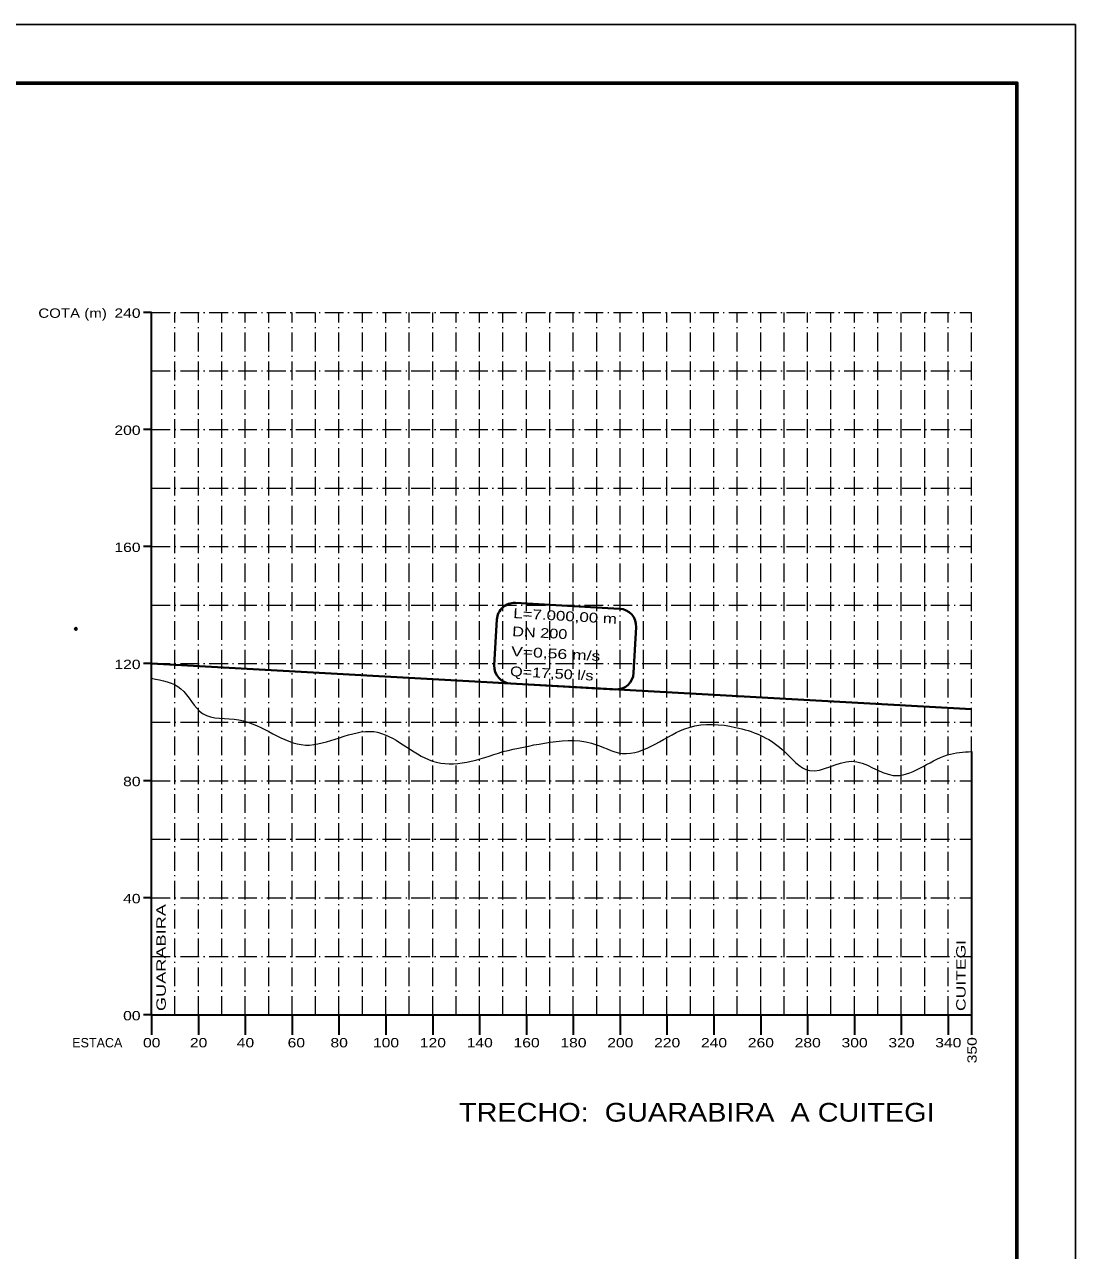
# Model space of a CAD drawing. Extents: x -4 to 42046, y -3 to 29697.
# Drawn here: x 33074 to 42046, y 19227 to 29697 of the extents above; entities that cross this region are included whole.
import ezdxf
from ezdxf.enums import TextEntityAlignment as Align

# ---------------------------------------------------------------- set-up
doc = ezdxf.new("R2010")
doc.units = 0
doc.header["$LTSCALE"] = 32
doc.header["$PDMODE"] = 32
doc.header["$PDSIZE"] = 16
doc.linetypes.add('DOT_DASHED', pattern=[7.7, 5, -1.2, 0.3, -1.2])
for name, color, linetype, lineweight in [('1', 7, 'DOT_DASHED', 13), ('24', 7, 'Continuous', 35), ('55', 7, 'Continuous', 13), ('62', 7, 'Continuous', 13), ('63', 7, 'Continuous', 25), ('9', 7, 'Continuous', 40)]:
    doc.layers.add(name, color=color, linetype=linetype, lineweight=lineweight)

msp = doc.modelspace()

# ---------------------------------------------------------------- linework, layer by layer
at = {"layer": '1'}
for p, q in [((34158.63, 27238.44), (41158.63, 27238.44)), ((34358.63, 21238.44), (34358.63, 27238.44)), ((34558.63, 21238.44), (34558.63, 27238.44)), ((34758.63, 21238.44), (34758.63, 27238.44)), ((34958.63, 21238.44), (34958.63, 27238.44)), ((35158.63, 21238.44), (35158.63, 27238.44)), ((35358.63, 21238.44), (35358.63, 27238.44)), ((35558.63, 21238.44), (35558.63, 27238.44)), ((35758.63, 21238.44), (35758.63, 27238.44)), ((35958.63, 21238.44), (35958.63, 27238.44)), ((36158.63, 21238.44), (36158.63, 27238.44)), ((36358.63, 21238.44), (36358.63, 27238.44)), ((36558.63, 21238.44), (36558.63, 27238.44)), ((36758.63, 21238.44), (36758.63, 27238.44)), ((36958.63, 21238.44), (36958.63, 27238.44)), ((37158.63, 21238.44), (37158.63, 27238.44)), ((37358.63, 21238.44), (37358.63, 27238.44)), ((37558.63, 21238.44), (37558.63, 27238.44)), ((37758.63, 21238.44), (37758.63, 27238.44)), ((37958.63, 21238.44), (37958.63, 27238.44)), ((38158.63, 21238.44), (38158.63, 27238.44)), ((38358.63, 21238.44), (38358.63, 27238.44)), ((38558.63, 21238.44), (38558.63, 27238.44)), ((38758.63, 21238.44), (38758.63, 27238.44)), ((38958.63, 21238.44), (38958.63, 27238.44)), ((39158.63, 21238.44), (39158.63, 27238.44)), ((39358.63, 21238.44), (39358.63, 27238.44)), ((39558.63, 21238.44), (39558.63, 27238.44)), ((39758.63, 21238.44), (39758.63, 27238.44)), ((39958.63, 21238.44), (39958.63, 27238.44)), ((40158.63, 21238.44), (40158.63, 27238.44)), ((40358.63, 21238.44), (40358.63, 27238.44)), ((40558.63, 21238.44), (40558.63, 27238.44)), ((40758.63, 21238.44), (40758.63, 27238.44)), ((40958.63, 21238.44), (40958.63, 27238.44)), ((41158.63, 21238.44), (41158.63, 27238.44)), ((34158.63, 26738.44), (41158.63, 26738.44)), ((34158.63, 26238.44), (41158.63, 26238.44)), ((34158.63, 25738.44), (41158.63, 25738.44)), ((34158.63, 25238.44), (41158.63, 25238.44)), ((34158.63, 24738.44), (41158.63, 24738.44)), ((34158.63, 24238.44), (41158.63, 24238.44)), ((34158.63, 23738.44), (41158.63, 23738.44)), ((34158.63, 23238.44), (41158.63, 23238.44)), ((34158.63, 22738.44), (41158.63, 22738.44)), ((34158.63, 22238.44), (41158.63, 22238.44)), ((34158.63, 21738.44), (41158.63, 21738.44))]:
    msp.add_line(p, q, dxfattribs=at)
at = {"layer": '55', "lineweight": 35}
msp.add_line((41158.63, 23488.44), (41158.63, 21238.44), dxfattribs=at)
at = {"layer": '55'}
for points in [[(34158.63, 24113.44), (34409.28, 24023.94), (34594.33, 23813.21), (34905.23, 23757.75), (35471.5, 23543.33), (36056.28, 23657.93), (36555.93, 23406.54), (37158.63, 23488.44)], [(37158.63, 23488.44), (37512.36, 23559.82), (37915.48, 23559.82), (38177.52, 23472.43), (38748.62, 23694.26), (39145.03, 23694.26), (39541.44, 23506.04), (39776.59, 23324.54), (40132.69, 23405.21), (40488.79, 23284.21), (40952.38, 23458.99), (41158.63, 23488.44)]]:
    msp.add_spline(points, degree=3, dxfattribs=at)
at = {"layer": '62', "lineweight": 35}
for p, q in [((34158.63, 27238.44), (34090.36, 27238.44)), ((34154.43, 27238.44), (34158.63, 27238.44)), ((34158.63, 21238.44), (34158.63, 27238.44)), ((34154.43, 26988.44), (34158.63, 26988.44)), ((34154.43, 26738.44), (34158.63, 26738.44)), ((34154.43, 26488.44), (34158.63, 26488.44)), ((34158.63, 26238.44), (34090.36, 26238.44)), ((34154.43, 26238.44), (34158.63, 26238.44)), ((34154.43, 25988.44), (34158.63, 25988.44)), ((34154.43, 25738.44), (34158.63, 25738.44)), ((34154.43, 25488.44), (34158.63, 25488.44)), ((34158.63, 25238.44), (34090.36, 25238.44)), ((34154.43, 25238.44), (34158.63, 25238.44)), ((34154.43, 24988.44), (34158.63, 24988.44)), ((34154.43, 24738.44), (34158.63, 24738.44)), ((34154.43, 24488.44), (34158.63, 24488.44)), ((34158.63, 24238.44), (34090.36, 24238.44)), ((34154.43, 24238.44), (34158.63, 24238.44)), ((34154.43, 23988.44), (34158.63, 23988.44)), ((34154.43, 23738.44), (34158.63, 23738.44)), ((34154.43, 23488.44), (34158.63, 23488.44)), ((34158.63, 23238.44), (34090.36, 23238.44)), ((34154.43, 23238.44), (34158.63, 23238.44)), ((34154.43, 22988.44), (34158.63, 22988.44)), ((34154.43, 22738.44), (34158.63, 22738.44)), ((34154.43, 22488.44), (34158.63, 22488.44)), ((34158.63, 22238.44), (34090.36, 22238.44)), ((34154.43, 22238.44), (34158.63, 22238.44)), ((34154.43, 21988.44), (34158.63, 21988.44)), ((34154.43, 21738.44), (34158.63, 21738.44)), ((34154.43, 21488.44), (34158.63, 21488.44)), ((34158.63, 21238.44), (34090.36, 21238.44)), ((34158.63, 21238.44), (34158.63, 21067.76)), ((34158.63, 21238.44), (41158.63, 21238.44)), ((34558.63, 21238.44), (34558.63, 21067.76)), ((34958.63, 21238.44), (34958.63, 21067.76)), ((35358.63, 21238.44), (35358.63, 21067.76)), ((35758.63, 21238.44), (35758.63, 21067.76)), ((36158.63, 21238.44), (36158.63, 21067.76)), ((36558.63, 21238.44), (36558.63, 21067.76)), ((36958.63, 21238.44), (36958.63, 21067.76)), ((37358.63, 21238.44), (37358.63, 21067.76)), ((37758.63, 21238.44), (37758.63, 21067.76)), ((38158.63, 21238.44), (38158.63, 21067.76)), ((38558.63, 21238.44), (38558.63, 21067.76)), ((38958.63, 21238.44), (38958.63, 21067.76)), ((39358.63, 21238.44), (39358.63, 21067.76)), ((39758.63, 21238.44), (39758.63, 21067.76)), ((40158.63, 21238.44), (40158.63, 21067.76)), ((40558.63, 21238.44), (40558.63, 21067.76)), ((40958.63, 21238.44), (40958.63, 21067.76)), ((41158.63, 21238.44), (41158.63, 21067.76))]:
    msp.add_line(p, q, dxfattribs=at)
at = {"layer": '62'}
for p, q in [((34154.43, 27188.44), (34158.63, 27188.44)), ((34154.43, 27138.44), (34158.63, 27138.44)), ((34154.43, 27088.44), (34158.63, 27088.44)), ((34154.43, 27038.44), (34158.63, 27038.44)), ((34154.43, 26938.44), (34158.63, 26938.44)), ((34154.43, 26888.44), (34158.63, 26888.44)), ((34154.43, 26838.44), (34158.63, 26838.44)), ((34154.43, 26788.44), (34158.63, 26788.44)), ((34154.43, 26688.44), (34158.63, 26688.44)), ((34154.43, 26638.44), (34158.63, 26638.44)), ((34154.43, 26588.44), (34158.63, 26588.44)), ((34154.43, 26538.44), (34158.63, 26538.44)), ((34154.43, 26438.44), (34158.63, 26438.44)), ((34154.43, 26388.44), (34158.63, 26388.44)), ((34154.43, 26338.44), (34158.63, 26338.44)), ((34154.43, 26288.44), (34158.63, 26288.44)), ((34154.43, 26188.44), (34158.63, 26188.44)), ((34154.43, 26138.44), (34158.63, 26138.44)), ((34154.43, 26088.44), (34158.63, 26088.44)), ((34154.43, 26038.44), (34158.63, 26038.44)), ((34154.43, 25938.44), (34158.63, 25938.44)), ((34154.43, 25888.44), (34158.63, 25888.44)), ((34154.43, 25838.44), (34158.63, 25838.44)), ((34154.43, 25788.44), (34158.63, 25788.44)), ((34154.43, 25688.44), (34158.63, 25688.44)), ((34154.43, 25638.44), (34158.63, 25638.44)), ((34154.43, 25588.44), (34158.63, 25588.44)), ((34154.43, 25538.44), (34158.63, 25538.44)), ((34154.43, 25438.44), (34158.63, 25438.44)), ((34154.43, 25388.44), (34158.63, 25388.44)), ((34154.43, 25338.44), (34158.63, 25338.44)), ((34154.43, 25288.44), (34158.63, 25288.44)), ((34154.43, 25188.44), (34158.63, 25188.44)), ((34154.43, 25138.44), (34158.63, 25138.44)), ((34154.43, 25088.44), (34158.63, 25088.44)), ((34154.43, 25038.44), (34158.63, 25038.44)), ((34154.43, 24938.44), (34158.63, 24938.44)), ((34154.43, 24888.44), (34158.63, 24888.44)), ((34154.43, 24838.44), (34158.63, 24838.44)), ((34154.43, 24788.44), (34158.63, 24788.44)), ((34154.43, 24688.44), (34158.63, 24688.44)), ((34154.43, 24638.44), (34158.63, 24638.44)), ((34154.43, 24588.44), (34158.63, 24588.44)), ((34154.43, 24538.44), (34158.63, 24538.44)), ((34154.43, 24438.44), (34158.63, 24438.44)), ((34154.43, 24388.44), (34158.63, 24388.44)), ((34154.43, 24338.44), (34158.63, 24338.44)), ((34154.43, 24288.44), (34158.63, 24288.44)), ((34154.43, 24188.44), (34158.63, 24188.44)), ((34154.43, 24138.44), (34158.63, 24138.44)), ((34154.43, 24088.44), (34158.63, 24088.44)), ((34154.43, 24038.44), (34158.63, 24038.44)), ((34154.43, 23938.44), (34158.63, 23938.44)), ((34154.43, 23888.44), (34158.63, 23888.44)), ((34154.43, 23838.44), (34158.63, 23838.44)), ((34154.43, 23788.44), (34158.63, 23788.44)), ((34154.43, 23688.44), (34158.63, 23688.44)), ((34154.43, 23638.44), (34158.63, 23638.44)), ((34154.43, 23588.44), (34158.63, 23588.44)), ((34154.43, 23538.44), (34158.63, 23538.44)), ((34154.43, 23438.44), (34158.63, 23438.44)), ((34154.43, 23388.44), (34158.63, 23388.44)), ((34154.43, 23338.44), (34158.63, 23338.44)), ((34154.43, 23288.44), (34158.63, 23288.44)), ((34154.43, 23188.44), (34158.63, 23188.44)), ((34154.43, 23138.44), (34158.63, 23138.44)), ((34154.43, 23088.44), (34158.63, 23088.44)), ((34154.43, 23038.44), (34158.63, 23038.44)), ((34154.43, 22938.44), (34158.63, 22938.44)), ((34154.43, 22888.44), (34158.63, 22888.44)), ((34154.43, 22838.44), (34158.63, 22838.44)), ((34154.43, 22788.44), (34158.63, 22788.44)), ((34154.43, 22688.44), (34158.63, 22688.44)), ((34154.43, 22638.44), (34158.63, 22638.44)), ((34154.43, 22588.44), (34158.63, 22588.44)), ((34154.43, 22538.44), (34158.63, 22538.44)), ((34154.43, 22438.44), (34158.63, 22438.44)), ((34154.43, 22388.44), (34158.63, 22388.44)), ((34154.43, 22338.44), (34158.63, 22338.44)), ((34154.43, 22288.44), (34158.63, 22288.44)), ((34154.43, 22188.44), (34158.63, 22188.44)), ((34154.43, 22138.44), (34158.63, 22138.44)), ((34154.43, 22088.44), (34158.63, 22088.44)), ((34154.43, 22038.44), (34158.63, 22038.44)), ((34154.43, 21938.44), (34158.63, 21938.44)), ((34154.43, 21888.44), (34158.63, 21888.44)), ((34154.43, 21838.44), (34158.63, 21838.44)), ((34154.43, 21788.44), (34158.63, 21788.44)), ((34154.43, 21688.44), (34158.63, 21688.44)), ((34154.43, 21638.44), (34158.63, 21638.44)), ((34154.43, 21588.44), (34158.63, 21588.44)), ((34154.43, 21538.44), (34158.63, 21538.44)), ((34154.43, 21438.44), (34158.63, 21438.44)), ((34154.43, 21388.44), (34158.63, 21388.44)), ((34154.43, 21338.44), (34158.63, 21338.44)), ((34154.43, 21288.44), (34158.63, 21288.44))]:
    msp.add_line(p, q, dxfattribs=at)
at = {"layer": '63'}
for p in [(-4.21, 29697.03), (42045.8, -2.97), (42045.8, -2.97)]:
    msp.add_line(p, (42045.8, 29697.03), dxfattribs=at)
msp.add_lwpolyline([(-4.21, -2.97), (42045.8, -2.97), (42045.8, 29697.03)], dxfattribs=at)
at = {"layer": '63', "lineweight": 60}
msp.add_lwpolyline([(1245.8, 29197.03), (41545.8, 29197.03), (41545.8, 497.03), (32795.79, 497.03)], dxfattribs=at)
at = {"layer": '63'}
msp.add_point((41545.8, 29197.03), dxfattribs=at)
at = {"layer": '9'}
for p, q in [((37264.6, 24756.83), (38154.08, 24707.3)), ((37106.49, 24615.4), (37084.8, 24225.74)), ((38295.5, 24549.19), (38273.81, 24159.53)), ((34158.63, 24238.44), (41158.63, 23848.67)), ((37226.23, 24067.63), (38115.7, 24018.1))]:
    msp.add_line(p, q, dxfattribs=at)
for centre, start, end in [((37256.26, 24607.06), 86.81296, 176.81296), ((38145.74, 24557.53), 356.81296, 86.81296), ((37234.57, 24217.4), 176.81296, 266.81296), ((38124.04, 24167.87), 266.81296, 356.81296)]:
    msp.add_arc(centre, 150, start, end, dxfattribs=at)
msp.add_point((33513.06, 24535.3), dxfattribs=at)

# ---------------------------------------------------------------- texts
at = {"layer": '24'}
for s, width, p in [('COTA (m)', 1.2, (33776.77, 27192.04)), ('240', 1.25, (34064.79, 27192.04)), ('200', 1.25, (34064.79, 26192.04)), ('160', 1.25, (34064.79, 25192.04)), ('120', 1.25, (34064.79, 24192.04)), ('80', 1.25, (34064.79, 23192.04)), ('40', 1.25, (34064.79, 22192.04)), ('00', 1.25, (34064.79, 21192.04))]:
    msp.add_text(s, height=80, dxfattribs=dict(at, width=width)).set_placement(p, align=Align.RIGHT)
for s, width, p in [('GUARABIRA', 1.45, (34280.31, 21271.36)), ('CUITEGI', 1.4, (41107.8, 21271.36))]:
    msp.add_text(s, height=80, rotation=90, dxfattribs=dict(at, width=width)).set_placement(p)
msp.add_text('ESTACA', height=80, dxfattribs=at).set_placement((33695.51, 20961.24), align=Align.CENTER)
for s, height, width, p in [('00', 80, 1.25, (34160.26, 20961.24)), ('20', 80, 1.25, (34560.26, 20961.24)), ('40', 80, 1.25, (34960.26, 20961.24)), ('60', 80, 1.25, (35394.58, 20961.24)), ('80', 80, 1.25, (35760.26, 20961.24)), ('100', 80, 1.25, (36160.26, 20961.24)), ('120', 80, 1.25, (36560.26, 20961.24)), ('140', 80, 1.25, (36960.26, 20961.24)), ('160', 80, 1.25, (37360.26, 20961.24)), ('180', 80, 1.25, (37760.26, 20961.24)), ('200', 80, 1.25, (38160.26, 20961.24)), ('220', 80, 1.25, (38560.26, 20961.24)), ('240', 80, 1.25, (38960.26, 20961.24)), ('260', 80, 1.25, (39360.26, 20961.24)), ('280', 80, 1.25, (39760.26, 20961.24)), ('300', 80, 1.25, (40160.26, 20961.24)), ('320', 80, 1.25, (40560.26, 20961.24)), ('340', 80, 1.25, (40960.26, 20961.24)), ('TRECHO:  GUARABIRA  A CUITEGI', 160, 1.15, (38813.33, 20326.92))]:
    msp.add_text(s, height=height, dxfattribs=dict(at, width=width)).set_placement(p, align=Align.CENTER)
at = {"layer": '24', "width": 1.25}
msp.add_text('350', height=80, rotation=90, dxfattribs=at).set_placement((41202.73, 20937.01), align=Align.CENTER)
at = {"layer": '9'}
for s, width, p in [('L=7.000,00 m', 1.3, (37244.54, 24628.28)), ('DN 200', 1.25, (37235.95, 24474.02)), ('V=0,56 m/s', 1.35, (37226.47, 24303.7)), ('Q=17,50 l/s', 1.25, (37216.99, 24133.37))]:
    msp.add_text(s, height=82.98, rotation=356.813, dxfattribs=dict(at, width=width)).set_placement(p)

doc.saveas('drawing.dxf')
